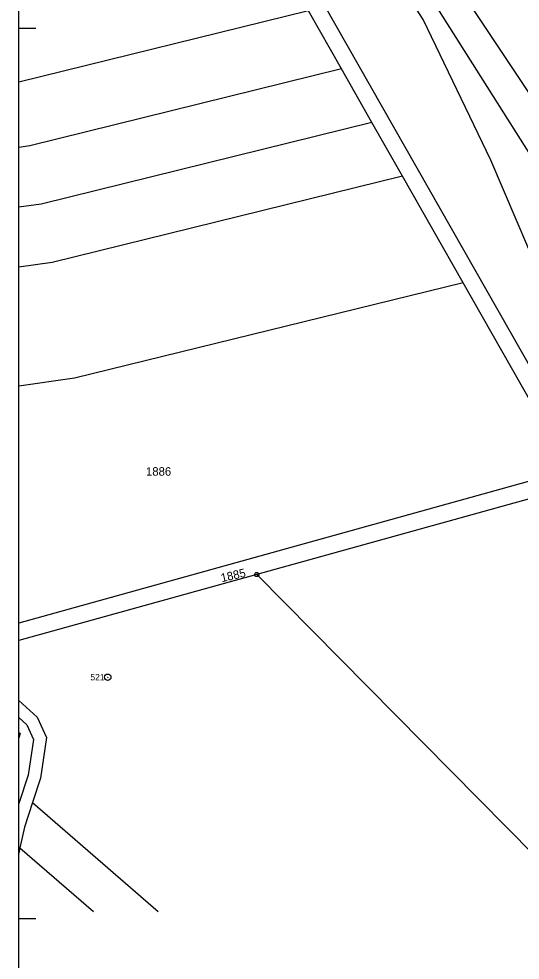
# Model space of a CAD drawing. Extents: x -601739 to -601442, y -1201912 to -1200862.
# Drawn here: x -601738.8 to -601620.6, y -1201712.1 to -1201490.1 of the extents above; entities that cross this region are included whole.
import ezdxf

# ---------------------------------------------------------------- set-up
doc = ezdxf.new("R2010")
doc.units = 0
for name, color, linetype in [('Hranice parcel', 7, 'Continuous'), ('Parcelní čísla', 7, 'Continuous'), ('x_rám', 7, 'Continuous'), ('Značky bodu BP', 7, 'Continuous')]:
    doc.layers.add(name, color=color, linetype=linetype)

msp = doc.modelspace()

# ---------------------------------------------------------------- linework, layer by layer
at = {"layer": 'Hranice parcel'}
for p, q in [((-601662.72, -1201501.91), (-601670.53, -1201488.18)), ((-601655.53, -1201514.55), (-601662.72, -1201501.91)), ((-601648.34, -1201527.2), (-601655.53, -1201514.55)), ((-601634.01, -1201552.38), (-601648.34, -1201527.2)), ((-601611.88, -1201591.29), (-601634.01, -1201552.38)), ((-601682.69, -1201621.14), (-601738.84, -1201636.73))]:
    msp.add_line(p, q, dxfattribs=at)
for points in [[(-601738.84, -1201327.84), (-601736.9, -1201330.72), (-601724.62, -1201347.71), (-601680.65, -1201411.14), (-601639.4, -1201476.17), (-601592.66, -1201546.3), (-601570.68, -1201592.44)], [(-601738.84, -1201338.85), (-601723.67, -1201361.08), (-601684.22, -1201417.67), (-601645.08, -1201479.64), (-601599.95, -1201551.04), (-601577.91, -1201595.98)], [(-601602.51, -1201597.25), (-601612.76, -1201557.83), (-601627.47, -1201523.39), (-601643.42, -1201490.21), (-601659.52, -1201465.35), (-601686.41, -1201425.71), (-601706.32, -1201392.22), (-601738.84, -1201347.04)], [(-601602.51, -1201597.25), (-601606.61, -1201592.45), (-601674.97, -1201472.32), (-601697.36, -1201436.46), (-601738.84, -1201377.24)], [(-601602.51, -1201597.25), (-601606.61, -1201592.45), (-601674.97, -1201472.32), (-601697.36, -1201436.46), (-601738.84, -1201377.24)], [(-601670.53, -1201488.18), (-601738.84, -1201505.02)], [(-601662.72, -1201501.91), (-601736.21, -1201520.04), (-601738.84, -1201520.4)], [(-601655.53, -1201514.55), (-601733.58, -1201533.81), (-601738.84, -1201534.53)], [(-601648.34, -1201527.2), (-601730.95, -1201547.58), (-601738.84, -1201548.66)], [(-601634.01, -1201552.38), (-601725.71, -1201574.86), (-601738.84, -1201576.71)], [(-601611.88, -1201591.29), (-601614.69, -1201598.11), (-601738.84, -1201632.59)], [(-601603.77, -1201605.53), (-601612.65, -1201601.69), (-601682.69, -1201621.14)], [(-601682.69, -1201621.14), (-601604.11, -1201700.64)], [(-601738.84, -1201650.82), (-601734.51, -1201654.77), (-601732.29, -1201659.59), (-601733.74, -1201669.16), (-601735.62, -1201674.91)], [(-601738.84, -1201654.88), (-601736.98, -1201656.58), (-601735.39, -1201660.03), (-601736.67, -1201668.46), (-601738.84, -1201675.11)], [(-601738.84, -1201658.37), (-601738.53, -1201658.62), (-601738.84, -1201659.63)], [(-601735.62, -1201674.91), (-601737.52, -1201680.74), (-601738.57, -1201685.58)], [(-601735.62, -1201674.91), (-601705.95, -1201700.64)], [(-601738.57, -1201685.58), (-601738.84, -1201686.83)], [(-601738.57, -1201685.58), (-601721.2, -1201700.64)]]:
    msp.add_lwpolyline(points, dxfattribs=at)
at = {"layer": 'x_rám'}
for p, q in [((-601734.8, -1201492.35), (-601738.84, -1201492.35)), ((-601734.8, -1201702.35), (-601738.84, -1201702.35))]:
    msp.add_line(p, q, dxfattribs=at)
msp.add_lwpolyline([(-601441.84, -1200862.35), (-601441.84, -1201912.35), (-601738.84, -1201912.35), (-601738.84, -1200862.35)], close=True, dxfattribs=at)
at = {"layer": 'Značky bodu BP'}
for centre, radius in [((-601682.69, -1201621.14), 0.5), ((-601682.69, -1201621.14), 0.0303), ((-601717.86, -1201645.36), 0.75), ((-601717.86, -1201645.36), 0.03)]:
    msp.add_circle(centre, radius, dxfattribs=at)

# ---------------------------------------------------------------- texts
at = {"layer": 'Parcelní čísla'}
msp.add_text('1886', height=2, dxfattribs=at).set_placement((-601708.84, -1201597.83))
msp.add_text('1885', height=2, rotation=13, dxfattribs=at).set_placement((-601690.94, -1201622.96))
at = {"layer": 'Značky bodu BP'}
msp.add_text('521', height=1.5, dxfattribs=at).set_placement((-601721.96, -1201646.11))

doc.saveas('drawing.dxf')
